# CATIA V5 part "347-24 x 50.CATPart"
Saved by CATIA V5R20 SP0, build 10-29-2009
Part number: 347-24 x 50
Definition: NONE
Nomenclature: 347-24 x 50
Source: Unknown
Description: 347-24 x 50
Bounding box of the stored display mesh (mm): x 0 to 50, y -18 to 18, z -18 to 18
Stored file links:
  C:\Users\Utente\Desktop\IO LAVORO\3D X SITO CF\X SITO\3D files 347\347-24 x 50.CATPart
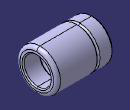
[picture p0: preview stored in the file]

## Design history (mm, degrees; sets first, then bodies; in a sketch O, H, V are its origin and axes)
Body1 "347-24 x 50" (main body)
  Solid1: solid without history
